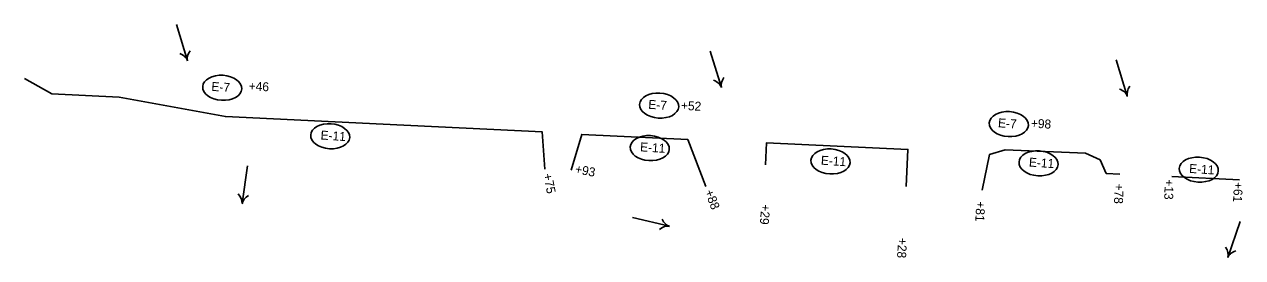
# Model space of a CAD drawing. Extents: x 669236 to 673912, y 735758 to 754788.
# Drawn here: x 669571 to 670423, y 743395 to 743558 of the extents above; entities that cross this region are included whole.
import ezdxf

# ---------------------------------------------------------------- set-up
doc = ezdxf.new("R2010")
doc.units = 0
doc.layers.add('R_Erosion_2', color=7, linetype='Continuous')
doc.layers.add('R_Flow Arrows', color=7, linetype='Continuous')

msp = doc.modelspace()

# ---------------------------------------------------------------- linework, layer by layer
at = {"layer": 'R_Erosion_2'}
msp.add_line((670323.02, 743463.18), (670327.23, 743453.73), dxfattribs=at)
for points in [[(669570.62, 743520.08), (669589.8, 743509.31), (669636.83, 743507.06), (669711.26, 743493.45), (669821.56, 743488.13), (669932.82, 743482.77), (669934.68, 743456.77)], [(669953.18, 743455.87), (669960.48, 743480.93), (670034.66, 743477.36)], [(670034.66, 743477.36), (670047.19, 743444.62)], [(670089.06, 743459.8), (670089.75, 743475.2), (670188.64, 743470.43), (670187.38, 743444.46)], [(670240.57, 743441.89), (670245.58, 743466.83), (670256.72, 743470.1)], [(670256.72, 743470.1), (670312.94, 743467.86), (670323.02, 743463.18)], [(670327.23, 743453.73), (670336.83, 743453.26)], [(670373.11, 743451.5), (670420.54, 743449.2)]]:
    msp.add_lwpolyline(points, dxfattribs=at)
for centre in [(669709.04, 743513.63), (670014.61, 743501.11), (670259.21, 743488.16), (669784.55, 743479.68), (670008.01, 743471.41), (670134.48, 743462.08), (670279.99, 743460.75), (670392.05, 743456.32)]:
    msp.add_ellipse(centre, major_axis=(13.67, -0.88), ratio=0.638788, dxfattribs=at)
at = {"layer": 'R_Flow Arrows'}
for p, q in [((669684.76, 743532.55), (669677.03, 743557.96)), ((670058.12, 743513.91), (670050.39, 743539.32)), ((670342.04, 743507.77), (670334.31, 743533.18)), ((669722.89, 743432.66), (669726.77, 743458.94)), ((670021.8, 743416.69), (669995.98, 743422.93)), ((670412.37, 743394.97), (670420.9, 743420.13))]:
    msp.add_line(p, q, dxfattribs=at)
for centre, major_axis, start_param, end_param in [((669704.17, 743537.99), (-19.29, -5.87), 5.662936, 6.259934), ((669665.55, 743526.43), (19.29, 5.87), 0.023252, 0.620249), ((670038.91, 743507.79), (19.29, 5.87), 0.023252, 0.620249), ((670077.53, 743519.35), (-19.29, -5.87), 5.662936, 6.259934), ((670361.45, 743513.21), (-19.29, -5.87), 5.662936, 6.259934), ((670322.83, 743501.66), (19.29, 5.87), 0.023252, 0.620249), ((669702.91, 743435.35), (19.94, -2.95), 0.023252, 0.620249), ((669742.76, 743429.28), (-19.94, 2.95), 5.662936, 6.259934), ((670026.96, 743436.18), (-4.73, -19.6), 5.662936, 6.259934), ((670017.33, 743397.04), (4.73, 19.6), 0.023252, 0.620249), ((670393.2, 743401.19), (19.09, -6.47), 0.023252, 0.620249), ((670431.32, 743388.08), (-19.09, 6.47), 5.662936, 6.259934)]:
    msp.add_ellipse(centre, major_axis=major_axis, ratio=0.5625, start_param=start_param, end_param=end_param, dxfattribs=at)

# ---------------------------------------------------------------- texts
at = {"layer": 'R_Erosion_2'}
for s, rotation, p in [('E-7', 356.2996, (669701.3, 743511.46)), ('+46', 356.99393, (669727.41, 743511.84)), ('E-7', 356.2996, (670006.87, 743498.94)), ('+52', 356.99393, (670029.75, 743498.2)), ('E-7', 356.2996, (670251.47, 743485.99)), ('+98', 356.99393, (670274.49, 743485.74)), ('E-11', 356.2996, (669777.67, 743477.46)), ('E-11', 356.2996, (670001.13, 743469.19)), ('E-11', 356.2996, (670127.59, 743459.85)), ('E-11', 356.2996, (670273.11, 743458.53)), ('+75', 281.47253, (669933.46, 743452.97)), ('+93', 349.27578, (669955.4, 743453.92)), ('E-11', 356.2996, (670385.17, 743454.1)), ('+78', 267.69292, (670333.32, 743446.69)), ('+13', 268.07959, (670368.33, 743449.63)), ('+61', 267.03724, (670416.73, 743447.84)), ('+88', 290.54678, (670046.41, 743441.06)), ('+29', 265.76519, (670086.08, 743432.28)), ('+81', 266.99393, (670236.47, 743434.31)), ('+28', 266.60881, (670181.84, 743408.76))]:
    msp.add_text(s, height=6.25, rotation=rotation, dxfattribs=at).set_placement(p)

doc.saveas('drawing.dxf')
